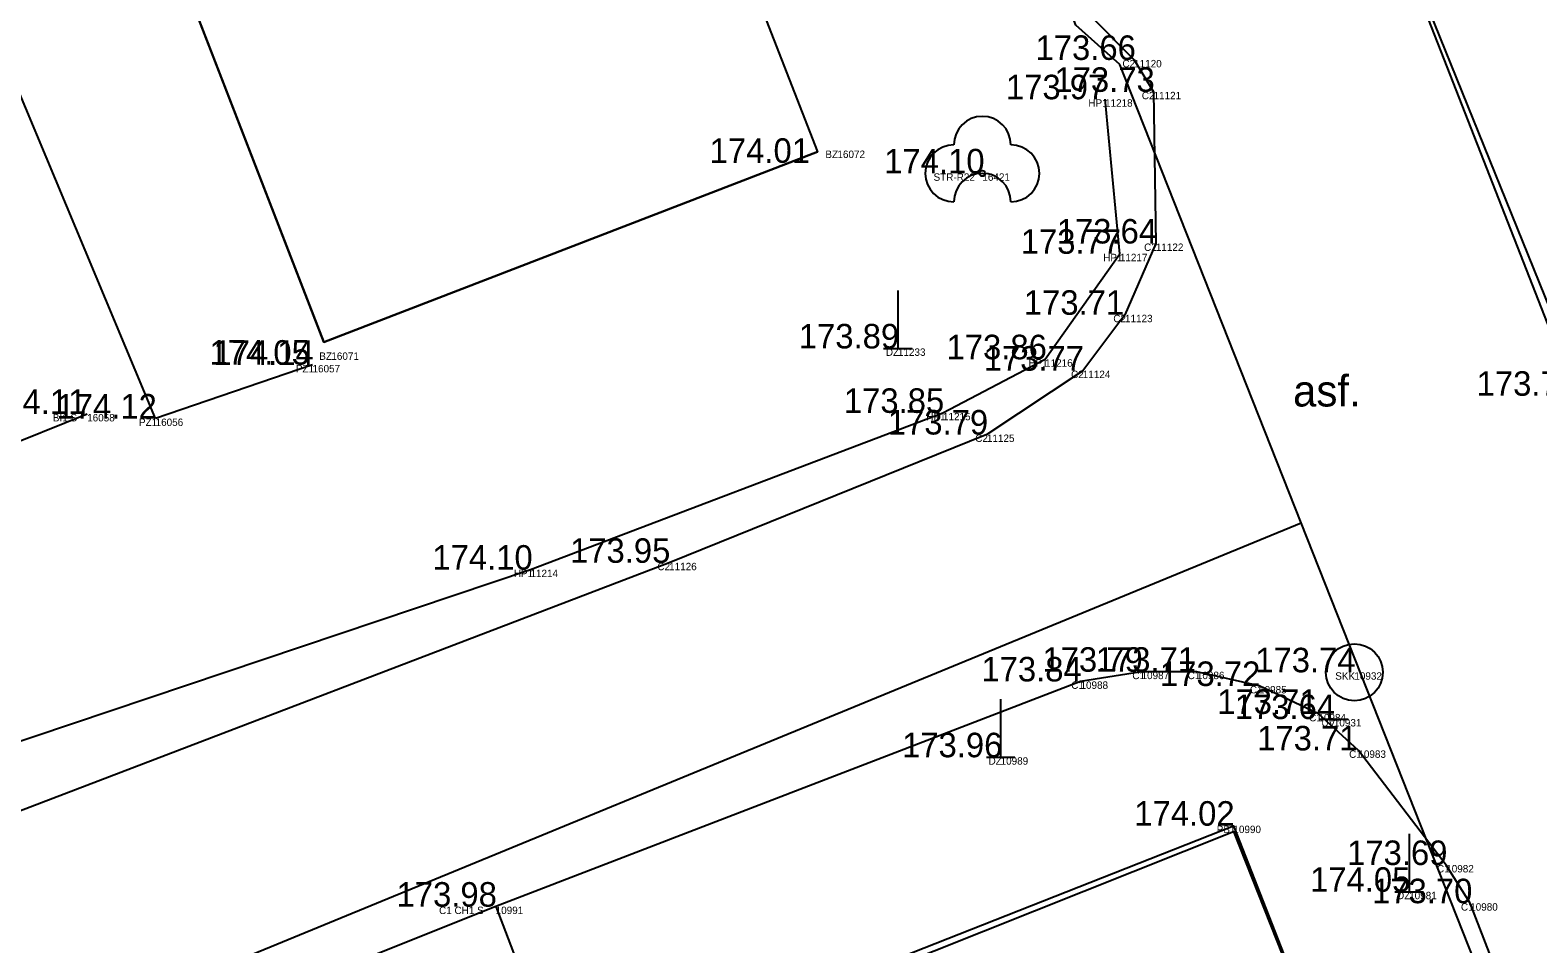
# Model space of a CAD drawing. Extents: x -566117 to -565580, y -1202428 to -1201938.
# Drawn here: x -565640.3 to -565613.87, y -1202153.92 to -1202137.9 of the extents above; entities that cross this region are included whole.
import ezdxf

# ---------------------------------------------------------------- set-up
doc = ezdxf.new("R2010")
doc.units = 0
for name, color, linetype in [('_0', 7, 'Continuous'), ('Bod', 7, 'Continuous'), ('BUOVY_NEMĚŘ', 7, 'Continuous'), ('Implicitní', 7, 'Continuous'), ('Kanalizace', 7, 'Continuous'), ('Katastr', 7, 'Continuous'), ('Kod', 7, 'Continuous'), ('Oplocení', 7, 'Continuous'), ('POMOC_POPIS', 7, 'Continuous'), ('Vrstva 61', 7, 'Continuous'), ('Výška', 7, 'Continuous'), ('ZELEŇ', 7, 'Continuous'), ('ZN_DOPLŇKOVÉ', 7, 'Continuous'), ('Zpevněné plohy', 7, 'Continuous'), ('Číslo', 7, 'Continuous')]:
    doc.layers.add(name, color=color, linetype=linetype)

# ---------------------------------------------------------------- blocks, each defined once
blk = doc.blocks.new('A$C69D74C1E')
at = {"layer": 'Katastr'}
blk.add_line((444.67, -58.02), (454.43, -82.19), dxfattribs=at)
for points in [[(446.91, -78.1), (443.73, -70.06), (442.96, -69.37), (431.86, -40.35), (433.02, -38.37), (428.19, -26.51), (420.97, -8.39), (414.6, 8.02), (406.54, 28.55), (397.51, 51.73), (392.1, 64.9), (383.47, 87.48), (375.32, 106.51), (374.71, 107), (373.34, 107.64), (371.88, 108.02), (370.59, 108.16), (369.35, 107.99)], [(436, -65.35), (438.43, -71.59), (429.78, -74.93), (423.97, -59.94), (418.18, -45), (426.77, -41.6), (429.2, -47.84), (429.44, -47.75), (430.49, -50.45), (430.25, -50.54), (432.6, -56.6), (435.01, -62.79), (435.25, -62.69), (436.25, -65.26), (436, -65.35)], [(397.89, -99.83), (397.46, -98.45), (446.91, -78.1)], [(464.96, -129.5), (465.88, -127.57), (465.89, -126.11), (446.91, -78.1)], [(417.61, -122.66), (408.07, -98.53), (445.72, -83.51), (455.52, -108.29)]]:
    blk.add_lwpolyline(points, dxfattribs=at)
blk = doc.blocks.new('STROM')
at = {"layer": 'ZELEŇ'}
blk.add_circle((0, 0), 0.05, dxfattribs=at)
for centre, start, end in [((0, 0.5), 0, 180), ((-0.5, 0), 90, 270), ((0.5, 0), 270, 90), ((0, -0.5), 0, 180)]:
    blk.add_arc(centre, 0.5, start, end, dxfattribs=at)
blk = doc.blocks.new('VP')
at = {"layer": 'Kanalizace'}
blk.add_line((-0.25, 0), (0.25, 0), dxfattribs=at)
blk = doc.blocks.new('SAK')
at = {"layer": 'Kanalizace'}
blk.add_circle((0, 0), 0.5, dxfattribs=at)
blk = doc.blocks.new('5.270_1')
at = {"layer": 'ZN_DOPLŇKOVÉ'}
for p, q in [((0, 1.018), (0, 0)), ((-0.25, 0), (0.25, 0))]:
    blk.add_line(p, q, dxfattribs=at)
blk = doc.blocks.new('POINT_DISPLAY')
at = {"layer": 'Implicitní'}
blk.add_line((0, 0), (0, 0), dxfattribs=at)

msp = doc.modelspace()

# ---------------------------------------------------------------- linework, layer by layer
at = {"layer": '_0'}
msp.add_line((-565639.3, -1202144.63), (-565642.11, -1202145.77), dxfattribs=at)
at = {"layer": 'BUOVY_NEMĚŘ'}
for points in [[(-565638.16, -1202110.04), (-565646.75, -1202113.44), (-565635.15, -1202143.37), (-565626.5, -1202140.03)], [(-565628.71, -1202133.62), (-565628.68, -1202133.7), (-565628.93, -1202133.79), (-565626.5, -1202140.03)]]:
    msp.add_lwpolyline(points, dxfattribs=at)
at = {"layer": 'Oplocení'}
msp.add_lwpolyline([(-565631.15, -1202156.56), (-565630.91, -1202156.47), (-565619.21, -1202151.85), (-565615.22, -1202162.06)], dxfattribs=at)
at = {"layer": 'ZELEŇ'}
for p, q in [((-565638.1, -1202144.71), (-565644.83, -1202128.62)), ((-565621.2, -1202141.82), (-565621.46, -1202139.11)), ((-565622.51, -1202143.67), (-565621.2, -1202141.82)), ((-565624.3, -1202144.61), (-565622.51, -1202143.67)), ((-565635.35, -1202143.77), (-565638.1, -1202144.71)), ((-565631.53, -1202147.36), (-565624.3, -1202144.61)), ((-565641.26, -1202150.63), (-565631.53, -1202147.36))]:
    msp.add_line(p, q, dxfattribs=at)
at = {"layer": 'Zpevněné plohy'}
for p, q in [((-565613.21, -1202144.31), (-565616.52, -1202135.84)), ((-565621.68, -1202137.68), (-565620.95, -1202138.42)), ((-565620.95, -1202138.42), (-565620.61, -1202138.98)), ((-565620.61, -1202138.98), (-565620.57, -1202141.64)), ((-565620.57, -1202141.64), (-565621.11, -1202142.89)), ((-565621.11, -1202142.89), (-565621.85, -1202143.87)), ((-565621.85, -1202143.87), (-565623.53, -1202144.99)), ((-565623.53, -1202144.99), (-565629.1, -1202147.24)), ((-565629.1, -1202147.24), (-565641.23, -1202151.88)), ((-565620.82, -1202149.15), (-565621.89, -1202149.32)), ((-565619.85, -1202149.15), (-565620.82, -1202149.15)), ((-565618.76, -1202149.4), (-565619.85, -1202149.15)), ((-565621.89, -1202149.32), (-565632.14, -1202153.27)), ((-565617.72, -1202149.89), (-565618.76, -1202149.4)), ((-565617.02, -1202150.53), (-565617.72, -1202149.89)), ((-565615.48, -1202152.54), (-565617.02, -1202150.53)), ((-565615.06, -1202153.21), (-565615.48, -1202152.54)), ((-565612.11, -1202160.79), (-565615.06, -1202153.21)), ((-565632.14, -1202153.27), (-565635.48, -1202154.6)), ((-565632.14, -1202153.27), (-565630.91, -1202156.47))]:
    msp.add_line(p, q, dxfattribs=at)

# ---------------------------------------------------------------- block references
at = {"layer": 'Bod'}
for p in [(-565620.95, -1202138.42), (-565620.61, -1202138.98), (-565621.46, -1202139.11), (-565626.15, -1202140.01), (-565623.61, -1202140.41), (-565621.2, -1202141.82), (-565620.57, -1202141.64), (-565621.11, -1202142.89), (-565635.02, -1202143.55), (-565625.09, -1202143.48), (-565622.51, -1202143.67), (-565635.35, -1202143.77), (-565621.85, -1202143.87), (-565639.3, -1202144.63), (-565638.1, -1202144.71), (-565624.3, -1202144.61), (-565623.53, -1202144.99), (-565631.53, -1202147.36), (-565629.1, -1202147.24), (-565620.82, -1202149.15), (-565619.85, -1202149.15), (-565617.09, -1202149.16), (-565621.89, -1202149.32), (-565618.76, -1202149.4), (-565617.72, -1202149.89), (-565617.45, -1202149.98), (-565617.02, -1202150.53), (-565623.29, -1202150.65), (-565619.21, -1202151.85), (-565615.48, -1202152.54), (-565616.13, -1202153.01), (-565615.06, -1202153.21), (-565632.14, -1202153.27)]:
    msp.add_blockref('POINT_DISPLAY', p, dxfattribs=at)
at = {"layer": 'Implicitní'}
msp.add_blockref('A$C69D74C1E', (-566064.93, -1202068.44), dxfattribs=at)
at = {"layer": 'Kanalizace'}
msp.add_blockref('SAK', (-565617.09, -1202149.16), dxfattribs=at)
at = {"layer": 'Vrstva 61'}
msp.add_blockref('VP', (-565617.45, -1202149.98), dxfattribs=at)
at = {"layer": 'ZELEŇ'}
msp.add_blockref('STROM', (-565623.61, -1202140.41), dxfattribs=at)
at = {"layer": 'ZN_DOPLŇKOVÉ'}
for p in [(-565625.09, -1202143.48), (-565623.29, -1202150.65), (-565616.13, -1202153.01)]:
    msp.add_blockref('5.270_1', p, dxfattribs=at)

# ---------------------------------------------------------------- texts
at = {"layer": 'Kod'}
for s, p in [('C2', (-565621.155, -1202138.55)), ('C2', (-565620.815, -1202139.11)), ('HP1', (-565621.752, -1202139.24)), ('BZ', (-565626.361, -1202140.14)), ('STR-R22', (-565624.465, -1202140.54)), ('HP1', (-565621.492, -1202141.95)), ('C2', (-565620.775, -1202141.77)), ('C2', (-565621.315, -1202143.02)), ('BZ', (-565635.231, -1202143.68)), ('DZ', (-565625.301, -1202143.61)), ('HP1', (-565622.802, -1202143.8)), ('PZ1', (-565635.642, -1202143.9)), ('C2', (-565622.055, -1202144)), ('BI1 S', (-565639.902, -1202144.76)), ('PZ1', (-565638.392, -1202144.84)), ('HP1', (-565624.592, -1202144.74)), ('C2', (-565623.735, -1202145.12)), ('HP1', (-565631.822, -1202147.49)), ('C2', (-565629.305, -1202147.37)), ('C1', (-565620.982, -1202149.28)), ('C1', (-565620.012, -1202149.28)), ('SKK', (-565617.425, -1202149.29)), ('C1', (-565622.052, -1202149.45)), ('C1', (-565618.922, -1202149.53)), ('C1', (-565617.882, -1202150.02)), ('UV', (-565617.667, -1202150.11)), ('C1', (-565617.182, -1202150.66)), ('DZ', (-565623.501, -1202150.78)), ('PB1', (-565619.502, -1202151.98)), ('C1', (-565615.642, -1202152.67)), ('DZ', (-565616.341, -1202153.14)), ('C1', (-565615.222, -1202153.34)), ('C1 CH1 S', (-565633.132, -1202153.4))]:
    msp.add_text(s, height=0.13, dxfattribs=at).set_placement(p)
at = {"layer": 'POMOC_POPIS'}
msp.add_text('asf.', height=0.55, dxfattribs=at).set_placement((-565618.164, -1202144.498))
at = {"layer": 'Výška'}
for s, p in [('173.66 ', (-565622.678, -1202138.42)), ('173.97 ', (-565623.197, -1202139.11)), ('173.73 ', (-565622.347, -1202138.98)), ('174.01 ', (-565628.39, -1202140.225)), ('174.10 ', (-565625.33, -1202140.41)), ('173.64 ', (-565622.307, -1202141.64)), ('173.77 ', (-565622.937, -1202141.82)), ('173.71 ', (-565622.883, -1202142.89)), ('173.89 ', (-565626.827, -1202143.48)), ('174.05 ', (-565637.156, -1202143.765)), ('174.14 ', (-565637.087, -1202143.77)), ('173.86 ', (-565624.238, -1202143.67)), ('173.77 ', (-565623.587, -1202143.87)), ('173.72 ', (-565614.947, -1202144.31)), ('174.11 ', (-565641.073, -1202144.63)), ('173.85 ', (-565626.037, -1202144.61)), ('174.12 ', (-565639.837, -1202144.71)), ('173.79 ', (-565625.267, -1202144.99)), ('173.95 ', (-565630.837, -1202147.24)), ('174.10 ', (-565633.25, -1202147.36)), ('173.79 ', (-565622.557, -1202149.15)), ('173.71 ', (-565621.623, -1202149.15)), ('173.74 ', (-565618.827, -1202149.16)), ('173.84 ', (-565623.627, -1202149.32)), ('173.72 ', (-565620.497, -1202149.4)), ('173.71 ', (-565619.493, -1202149.89)), ('173.64 ', (-565619.187, -1202149.98)), ('173.96 ', (-565625.018, -1202150.65)), ('173.71 ', (-565618.793, -1202150.53)), ('174.02 ', (-565620.947, -1202151.85)), ('173.69 ', (-565617.217, -1202152.54)), ('174.05 ', (-565617.867, -1202153.01)), ('173.98 ', (-565633.877, -1202153.27)), ('173.70 ', (-565616.78, -1202153.21))]:
    msp.add_text(s, height=0.43, dxfattribs=at).set_placement(p)
at = {"layer": 'Číslo'}
for s, p in [('11120', (-565620.95, -1202138.55)), ('11121', (-565620.61, -1202139.11)), ('11218', (-565621.46, -1202139.24)), ('16072', (-565626.15, -1202140.14)), ('16421', (-565623.61, -1202140.54)), ('11217', (-565621.2, -1202141.95)), ('11122', (-565620.57, -1202141.77)), ('11123', (-565621.11, -1202143.02)), ('16071', (-565635.02, -1202143.68)), ('11233', (-565625.09, -1202143.61)), ('11216', (-565622.51, -1202143.8)), ('16057', (-565635.35, -1202143.9)), ('11124', (-565621.85, -1202144)), ('16058', (-565639.3, -1202144.76)), ('16056', (-565638.1, -1202144.84)), ('11215', (-565624.3, -1202144.74)), ('11125', (-565623.53, -1202145.12)), ('11214', (-565631.53, -1202147.49)), ('11126', (-565629.1, -1202147.37)), ('10987', (-565620.82, -1202149.28)), ('10986', (-565619.85, -1202149.28)), ('10932', (-565617.09, -1202149.29)), ('10988', (-565621.89, -1202149.45)), ('10985', (-565618.76, -1202149.53)), ('10984', (-565617.72, -1202150.02)), ('10931', (-565617.45, -1202150.11)), ('10983', (-565617.02, -1202150.66)), ('10989', (-565623.29, -1202150.78)), ('10990', (-565619.21, -1202151.98)), ('10982', (-565615.48, -1202152.67)), ('10981', (-565616.13, -1202153.14)), ('10980', (-565615.06, -1202153.34)), ('10991', (-565632.14, -1202153.4))]:
    msp.add_text(s, height=0.13, dxfattribs=at).set_placement(p)

doc.saveas('drawing.dxf')
